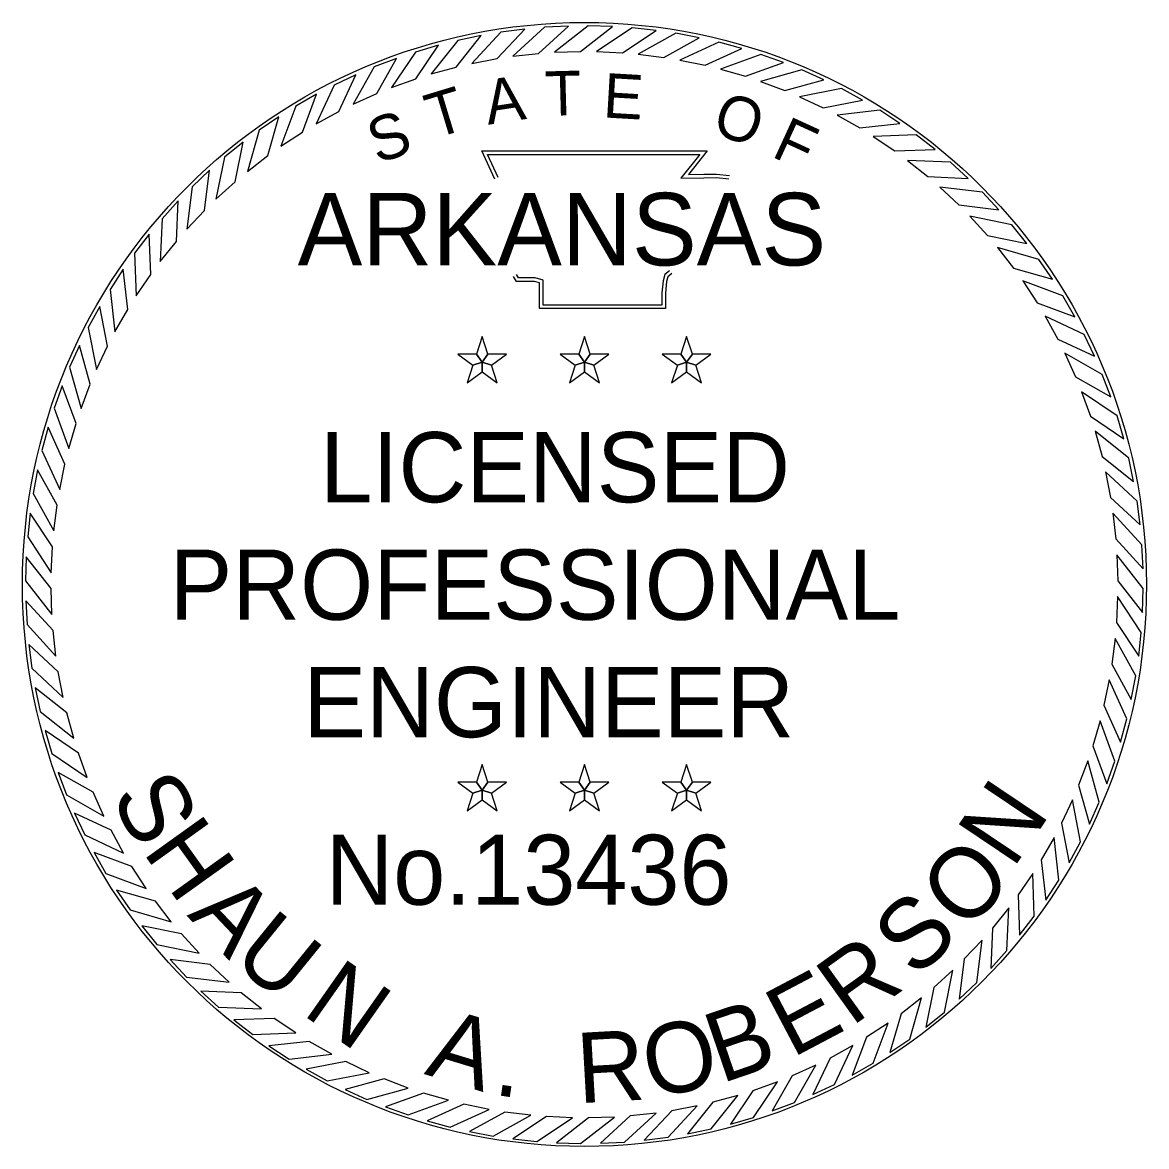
# Model space of a CAD drawing. Extents: x 0 to 19, y -0.6 to 11.2.
# Drawn here: x 17.813 to 19.013, y 6.33 to 7.53 of the extents above; entities that cross this region are included whole.
import ezdxf

# ---------------------------------------------------------------- set-up
doc = ezdxf.new("R2010")
doc.units = 0
doc.layers.add('G-ANNO-SYMB', color=7, linetype='Continuous')
doc.layers.add('G-No Plot-Stamp-1', color=7, linetype='Continuous')

msp = doc.modelspace()

# ---------------------------------------------------------------- linework, layer by layer
at = {"layer": 'G-ANNO-SYMB'}
for points in [[(18.3955, 7.5265), (18.3699, 7.5252), (18.3362, 7.4944), (18.3637, 7.4974)], [(18.4424, 7.526), (18.4167, 7.5268), (18.3807, 7.4986), (18.4084, 7.4995)], [(18.489, 7.5219), (18.4635, 7.5246), (18.4254, 7.4994), (18.4531, 7.4981)], [(18.3024, 7.5165), (18.2773, 7.5112), (18.2489, 7.4755), (18.2756, 7.4828)], [(18.3488, 7.5234), (18.3233, 7.5201), (18.2922, 7.4866), (18.3194, 7.4918)], [(18.5352, 7.514), (18.51, 7.5188), (18.47, 7.4966), (18.4975, 7.4931)], [(18.2568, 7.5061), (18.2322, 7.4988), (18.2066, 7.4609), (18.2327, 7.4703)], [(18.5806, 7.5026), (18.5559, 7.5093), (18.5143, 7.4903), (18.5414, 7.4847)], [(18.2121, 7.4921), (18.1881, 7.4829), (18.1656, 7.4431), (18.1908, 7.4546)], [(18.625, 7.4877), (18.6009, 7.4963), (18.5579, 7.4806), (18.5845, 7.4729)], [(18.6681, 7.4693), (18.6447, 7.4798), (18.6006, 7.4675), (18.6266, 7.4578)], [(18.1686, 7.4746), (18.1454, 7.4636), (18.1261, 7.4222), (18.1504, 7.4355)], [(18.1266, 7.4538), (18.1044, 7.441), (18.0884, 7.3982), (18.1115, 7.4134)], [(18.7096, 7.4476), (18.6871, 7.4599), (18.6422, 7.4511), (18.6673, 7.4393)], [(18.0864, 7.4297), (18.0653, 7.4153), (18.0527, 7.3713), (18.0746, 7.3883)], [(18.7493, 7.4227), (18.7278, 7.4367), (18.6824, 7.4315), (18.7065, 7.4178)], [(18.7869, 7.3947), (18.7666, 7.4104), (18.7209, 7.4088), (18.7438, 7.3932)], [(18.0483, 7.4026), (18.0283, 7.3865), (18.0192, 7.3417), (18.0397, 7.3604)], [(18.8222, 7.3639), (18.8032, 7.3811), (18.7575, 7.3831), (18.7791, 7.3658)], [(18.0123, 7.3726), (17.9937, 7.355), (17.9881, 7.3096), (18.0071, 7.3298)], [(18.855, 7.3304), (18.8374, 7.3491), (18.792, 7.3547), (18.8122, 7.3357)], [(17.9788, 7.3398), (17.9616, 7.3208), (17.9596, 7.2751), (17.977, 7.2967)], [(18.885, 7.2945), (18.8689, 7.3145), (18.8241, 7.3236), (18.8428, 7.3031)], [(17.948, 7.3045), (17.9324, 7.2842), (17.934, 7.2385), (17.9495, 7.2614)], [(18.9121, 7.2563), (18.8977, 7.2775), (18.8537, 7.2901), (18.8707, 7.2682)], [(17.9201, 7.2669), (17.9061, 7.2454), (17.9113, 7.2), (17.925, 7.2241)], [(18.9362, 7.2161), (18.9234, 7.2384), (18.8806, 7.2544), (18.8958, 7.2312)], [(17.8952, 7.2272), (17.8829, 7.2047), (17.8916, 7.1598), (17.9034, 7.1849)], [(18.957, 7.1742), (18.946, 7.1973), (18.9046, 7.2167), (18.9179, 7.1924)], [(18.3035, 7.1677), (18.3096, 7.1762), (18.3035, 7.195), (18.2974, 7.1762)], [(18.4126, 7.1677), (18.4187, 7.1762), (18.4126, 7.195), (18.4065, 7.1762)], [(18.5217, 7.1677), (18.5278, 7.1762), (18.5217, 7.195), (18.5155, 7.1762)], [(17.8735, 7.1857), (17.863, 7.1623), (17.8752, 7.1183), (17.885, 7.1442)], [(18.3035, 7.1677), (18.2974, 7.1762), (18.2775, 7.1762), (18.2936, 7.1645)], [(18.3035, 7.1677), (18.3134, 7.1645), (18.3294, 7.1762), (18.3096, 7.1762)], [(18.4126, 7.1677), (18.4065, 7.1762), (18.3866, 7.1762), (18.4027, 7.1645)], [(18.4126, 7.1677), (18.4225, 7.1645), (18.4385, 7.1762), (18.4187, 7.1762)], [(18.5217, 7.1677), (18.5155, 7.1762), (18.4957, 7.1762), (18.5118, 7.1645)], [(18.5217, 7.1677), (18.5316, 7.1645), (18.5476, 7.1762), (18.5278, 7.1762)], [(18.9745, 7.1307), (18.9653, 7.1547), (18.9255, 7.1772), (18.9369, 7.1519)], [(18.3035, 7.1677), (18.2936, 7.1645), (18.2875, 7.1457), (18.3035, 7.1573)], [(18.3035, 7.1677), (18.3035, 7.1573), (18.3195, 7.1457), (18.3134, 7.1645)], [(18.4126, 7.1677), (18.4027, 7.1645), (18.3965, 7.1457), (18.4126, 7.1573)], [(18.4126, 7.1677), (18.4126, 7.1573), (18.4286, 7.1457), (18.4225, 7.1645)], [(18.5217, 7.1677), (18.5118, 7.1645), (18.5056, 7.1457), (18.5217, 7.1573)], [(18.5217, 7.1677), (18.5217, 7.1573), (18.5377, 7.1457), (18.5316, 7.1645)], [(17.8551, 7.1426), (17.8465, 7.1185), (17.8621, 7.0755), (17.8698, 7.1021)], [(18.9885, 7.086), (18.9812, 7.1106), (18.9433, 7.1362), (18.9527, 7.1101)], [(17.8401, 7.0982), (17.8334, 7.0735), (17.8524, 7.0319), (17.858, 7.059)], [(18.9989, 7.0403), (18.9936, 7.0654), (18.9579, 7.0939), (18.9652, 7.0672)], [(17.8287, 7.0528), (17.824, 7.0276), (17.8462, 6.9876), (17.8496, 7.0151)], [(19.0058, 6.994), (19.0025, 7.0194), (18.969, 7.0506), (18.9742, 7.0234)], [(17.8209, 7.0066), (17.8182, 6.9811), (17.8434, 6.943), (17.8447, 6.9707)], [(19.0089, 6.9472), (19.0076, 6.9729), (18.9768, 7.0066), (18.9798, 6.979)], [(19.0084, 6.9004), (19.0092, 6.926), (18.981, 6.9621), (18.9819, 6.9344)], [(17.8167, 6.96), (17.816, 6.9343), (17.8441, 6.8983), (17.8433, 6.926)], [(17.8162, 6.9131), (17.8175, 6.8875), (17.8484, 6.8538), (17.8454, 6.8813)], [(19.0043, 6.8537), (19.007, 6.8792), (18.9818, 6.9174), (18.9805, 6.8897)], [(17.8194, 6.8664), (17.8227, 6.841), (17.8561, 6.8098), (17.8509, 6.837)], [(18.9964, 6.8075), (19.0012, 6.8328), (18.979, 6.8728), (18.9755, 6.8453)], [(18.985, 6.7621), (18.9917, 6.7869), (18.9727, 6.8285), (18.9671, 6.8014)], [(17.8262, 6.8201), (17.8315, 6.7949), (17.8673, 6.7665), (17.86, 6.7932)], [(18.9701, 6.7177), (18.9787, 6.7419), (18.963, 6.7849), (18.9553, 6.7582)], [(17.8367, 6.7744), (17.8439, 6.7498), (17.8818, 6.7242), (17.8724, 6.7503)], [(18.3035, 6.7109), (18.3096, 6.7194), (18.3035, 6.7382), (18.2974, 6.7194)], [(18.4126, 6.7109), (18.4187, 6.7194), (18.4126, 6.7382), (18.4065, 6.7194)], [(18.5217, 6.7109), (18.5278, 6.7194), (18.5217, 6.7382), (18.5155, 6.7194)], [(18.9517, 6.6746), (18.9622, 6.6981), (18.9499, 6.7421), (18.9401, 6.7162)], [(17.8507, 6.7297), (17.8598, 6.7057), (17.8996, 6.6832), (17.8882, 6.7085)], [(18.3035, 6.7109), (18.2974, 6.7194), (18.2775, 6.7194), (18.2936, 6.7077)], [(18.3035, 6.7109), (18.2936, 6.7077), (18.2875, 6.6889), (18.3035, 6.7005)], [(18.3035, 6.7109), (18.3134, 6.7077), (18.3294, 6.7194), (18.3096, 6.7194)], [(18.3035, 6.7109), (18.3035, 6.7005), (18.3195, 6.6889), (18.3134, 6.7077)], [(18.4126, 6.7109), (18.4065, 6.7194), (18.3866, 6.7194), (18.4027, 6.7077)], [(18.4126, 6.7109), (18.4027, 6.7077), (18.3965, 6.6889), (18.4126, 6.7005)], [(18.4126, 6.7109), (18.4225, 6.7077), (18.4385, 6.7194), (18.4187, 6.7194)], [(18.4126, 6.7109), (18.4126, 6.7005), (18.4286, 6.6889), (18.4225, 6.7077)], [(18.5217, 6.7109), (18.5155, 6.7194), (18.4957, 6.7194), (18.5118, 6.7077)], [(18.5217, 6.7109), (18.5118, 6.7077), (18.5056, 6.6889), (18.5217, 6.7005)], [(18.5217, 6.7109), (18.5316, 6.7077), (18.5476, 6.7194), (18.5278, 6.7194)], [(18.5217, 6.7109), (18.5217, 6.7005), (18.5377, 6.6889), (18.5316, 6.7077)], [(18.93, 6.6331), (18.9423, 6.6556), (18.9335, 6.7005), (18.9217, 6.6755)], [(17.8681, 6.6862), (17.8791, 6.663), (17.9206, 6.6437), (17.9072, 6.668)], [(18.9051, 6.5935), (18.9191, 6.6149), (18.9139, 6.6604), (18.9002, 6.6363)], [(17.889, 6.6443), (17.9017, 6.622), (17.9446, 6.606), (17.9294, 6.6292)], [(18.8771, 6.5559), (18.8928, 6.5762), (18.8912, 6.6219), (18.8756, 6.5989)], [(17.913, 6.6041), (17.9275, 6.5829), (17.9715, 6.5703), (17.9545, 6.5922)], [(18.8463, 6.5206), (18.8635, 6.5396), (18.8655, 6.5853), (18.8482, 6.5636)], [(17.9401, 6.5659), (17.9562, 6.5459), (18.0011, 6.5368), (17.9824, 6.5573)], [(18.8128, 6.4878), (18.8315, 6.5054), (18.8371, 6.5508), (18.8181, 6.5306)], [(17.9702, 6.5299), (17.9878, 6.5113), (18.0332, 6.5057), (18.013, 6.5247)], [(18.7769, 6.4577), (18.7969, 6.4738), (18.806, 6.5187), (18.7855, 6.5)], [(18.003, 6.4964), (18.022, 6.4792), (18.0677, 6.4772), (18.046, 6.4946)], [(18.7387, 6.4306), (18.7599, 6.4451), (18.7725, 6.4891), (18.7506, 6.4721)], [(18.0382, 6.4656), (18.0586, 6.45), (18.1043, 6.4516), (18.0813, 6.4671)], [(18.6985, 6.4066), (18.7208, 6.4193), (18.7368, 6.4622), (18.7136, 6.447)], [(18.0758, 6.4377), (18.0973, 6.4237), (18.1428, 6.4289), (18.1187, 6.4426)], [(18.6565, 6.3858), (18.6797, 6.3967), (18.699, 6.4382), (18.6748, 6.4248)], [(18.1155, 6.4128), (18.138, 6.4005), (18.1829, 6.4092), (18.1578, 6.421)], [(18.6131, 6.3683), (18.637, 6.3774), (18.6596, 6.4172), (18.6343, 6.4058)], [(18.157, 6.3911), (18.1804, 6.3806), (18.2245, 6.3928), (18.1986, 6.4026)], [(18.5684, 6.3543), (18.593, 6.3615), (18.6186, 6.3994), (18.5925, 6.39)], [(18.2001, 6.3727), (18.2243, 6.3641), (18.2673, 6.3797), (18.2406, 6.3874)], [(18.5227, 6.3438), (18.5478, 6.3491), (18.5763, 6.3849), (18.5495, 6.3776)], [(18.2445, 6.3578), (18.2693, 6.3511), (18.3109, 6.37), (18.2837, 6.3756)], [(18.4764, 6.337), (18.5018, 6.3403), (18.533, 6.3737), (18.5058, 6.3685)], [(18.2899, 6.3463), (18.3152, 6.3416), (18.3552, 6.3638), (18.3277, 6.3672)], [(18.3361, 6.3385), (18.3616, 6.3358), (18.3998, 6.361), (18.3721, 6.3623)], [(18.3828, 6.3343), (18.4084, 6.3336), (18.4445, 6.3618), (18.4168, 6.3609)], [(18.4296, 6.3338), (18.4553, 6.3351), (18.489, 6.366), (18.4614, 6.363)]]:
    msp.add_lwpolyline(points, close=True, dxfattribs=at)
for points in [[(18.317, 7.3632), (18.3031, 7.3933), (18.5437, 7.3934), (18.5236, 7.3682), (18.54, 7.3684), (18.5536, 7.3686), (18.5673, 7.3671)], [(18.3205, 7.3648), (18.309, 7.3895), (18.5358, 7.3896), (18.5156, 7.3643), (18.54, 7.3646), (18.5534, 7.3648), (18.5669, 7.3633)], [(18.5058, 7.2623), (18.5017, 7.259), (18.5003, 7.254), (18.499, 7.2415), (18.499, 7.2249), (18.3647, 7.2249), (18.3647, 7.2474), (18.3647, 7.2523), (18.3592, 7.254), (18.3401, 7.254), (18.3367, 7.2592)], [(18.5034, 7.2653), (18.4984, 7.2612), (18.4966, 7.2547), (18.4952, 7.2417), (18.4952, 7.2287), (18.3685, 7.2287), (18.3685, 7.2474), (18.3685, 7.2552), (18.3598, 7.2578), (18.3422, 7.2578), (18.3399, 7.2613)]]:
    msp.add_lwpolyline(points, dxfattribs=at)
at = {"layer": 'G-No Plot-Stamp-1'}
msp.add_circle((18.4126, 6.9304), 0.6, dxfattribs=at)

# ---------------------------------------------------------------- texts
at = {"layer": 'G-ANNO-SYMB'}
for s, height, rotation, p in [('T', 0.0475, 1.4789, (18.371, 7.4306)), ('E', 0.0475, 356.672, (18.4317, 7.4291)), ('A', 0.0475, 8.6788, (18.3097, 7.4211)), ('T', 0.0475, 16.9015, (18.252, 7.4061)), ('O', 0.0475, 341.2218, (18.547, 7.4128)), ('S', 0.0475, 19.7726, (18.1917, 7.379)), ('F', 0.0475, 335.3628, (18.6109, 7.3878)), ('ARKANSAS', 0.07747, 360, (18.1064, 7.271)), ('LICENSED', 0.075, 360, (18.1304, 7.0181)), ('PROFESSIONAL', 0.075, 360, (17.9697, 6.8927)), ('ENGINEER', 0.075, 360, (18.1126, 6.7673)), ('S', 0.075, 298.1636, (17.9058, 6.7042)), ('N', 0.075, 56.1007, (18.87, 6.6258)), ('H', 0.075, 305.619, (17.94, 6.6454)), ('No.13436', 0.0747, 360, (18.1363, 6.5885)), ('O', 0.075, 44.7757, (18.8179, 6.5583)), ('A', 0.075, 313.4472, (17.9876, 6.577)), ('S', 0.075, 43.4878, (18.7664, 6.5086)), ('U', 0.075, 320.9026, (18.0343, 6.5281)), ('R', 0.075, 35.6597, (18.6974, 6.4576)), ('N', 0.075, 324.9326, (18.1099, 6.4722)), ('E', 0.075, 27.8315, (18.634, 6.4244)), ('B', 0.075, 18.885, (18.5583, 6.3973)), ('A', 0.075, 343.0991, (18.2407, 6.4079)), ('O', 0.075, 11.4296, (18.4831, 6.3814)), ('R', 0.075, 3.2287, (18.4063, 6.3765)), ('.', 0.075, 351.3, (18.3144, 6.386))]:
    msp.add_text(s, height=height, rotation=rotation, dxfattribs=at).set_placement(p)

doc.saveas('drawing.dxf')
